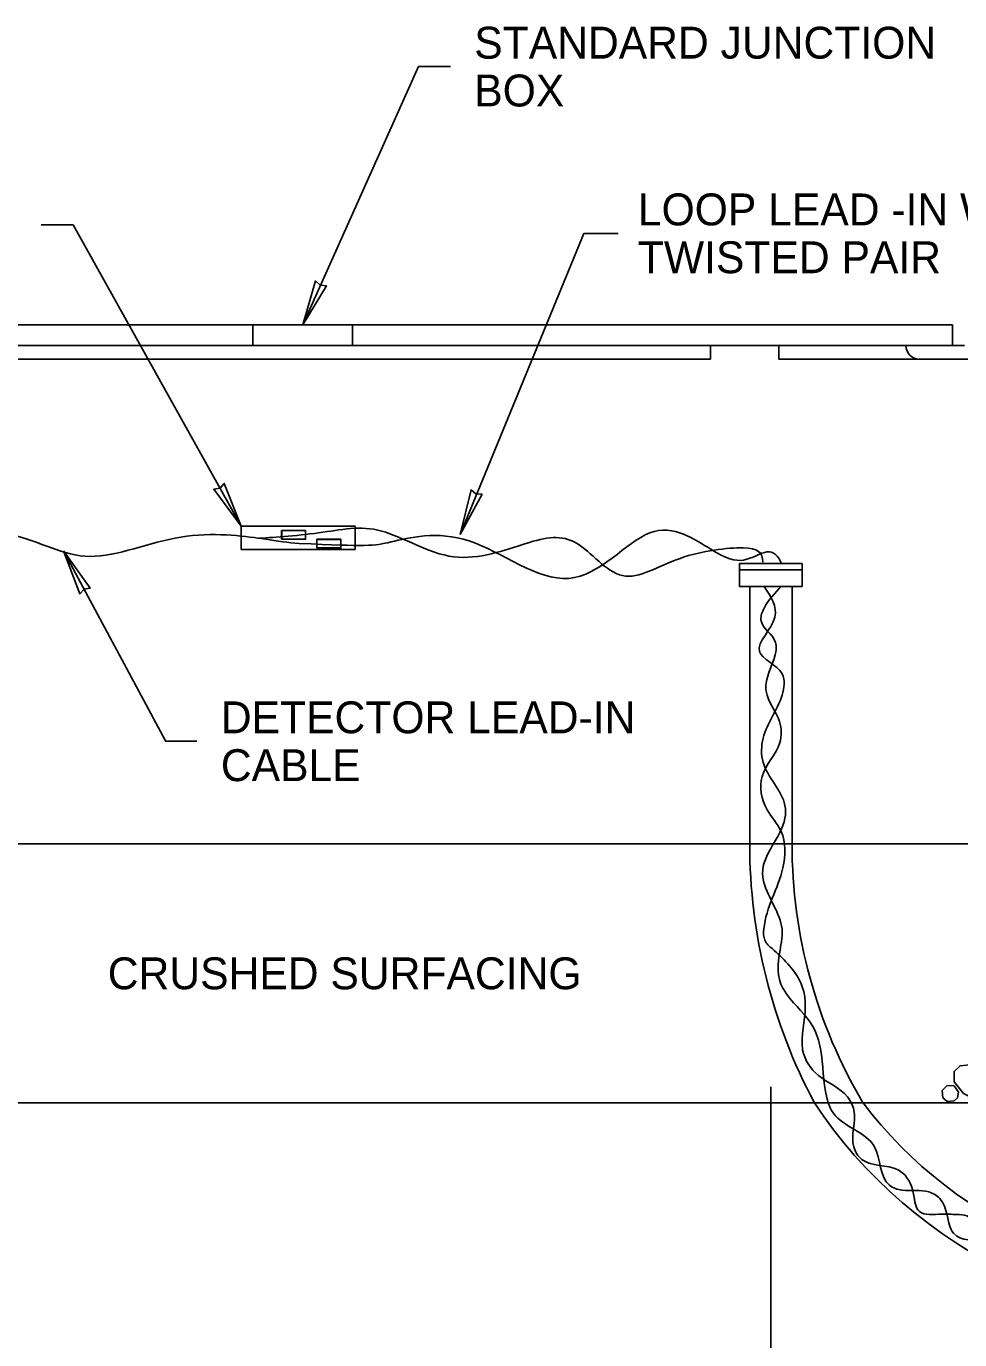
# Model space of a CAD drawing. Extents: x 99862 to 103151, y 100000 to 108153.
# Drawn here: x 101003 to 101472, y 100351 to 101010 of the extents above; entities that cross this region are included whole.
import ezdxf

# ---------------------------------------------------------------- set-up
doc = ezdxf.new("R2010")
doc.units = 0
for name, color, linetype in [('Level 10', 7, 'Continuous'), ('Level 11', 7, 'Continuous'), ('Level 12', 7, 'Continuous'), ('Level 13', 7, 'Continuous'), ('Level 15', 7, 'Continuous'), ('Level 2', 7, 'Continuous'), ('Level 20', 7, 'Continuous'), ('Level 22', 7, 'Continuous'), ('Level 3', 7, 'Continuous'), ('Level 5', 7, 'Continuous')]:
    doc.layers.add(name, color=color, linetype=linetype)

msp = doc.modelspace()

# ---------------------------------------------------------------- linework, layer by layer
at = {"layer": 'Level 10'}
for p, q in [((101366.46, 100599.88), (101366.46, 100729.02)), ((101387.71, 100599.88), (101387.71, 100729.02))]:
    msp.add_line(p, q, dxfattribs=at)
for radius, end in [(276.25, 208.06023), (255, 210.63538)]:
    msp.add_arc((101642.71, 100599.88), radius, 180, end, dxfattribs=at)
for centre, major_axis, ratio, start_param in [((101642.71, 100576.59), (276.25, 0), 0.820889, 3.63155), ((101642.71, 100572.63), (255, 0), 0.79044, 3.67655)]:
    msp.add_ellipse(centre, major_axis=major_axis, ratio=ratio, start_param=start_param, end_param=4.712389, dxfattribs=at)
at = {"layer": 'Level 11'}
for points in [[(100765.96, 100599.88), (101570.21, 100599.88), (101570.21, 100469.88), (100765.96, 100469.88)], [(101485.29, 100486.31), (101478.37, 100489.06), (101472.02, 100488.51), (101469, 100485.64), (101469.09, 100480.48), (101473.68, 100474.62), (101480.76, 100471.08), (101487.44, 100470.96), (101491.19, 100473.63), (101491.55, 100478.95), (101488.5, 100483.71), (101485.01, 100486.49)], [(101471.25, 100475.22), (101469.03, 100478.37), (101465.49, 100478.57), (101463.02, 100476.02), (101463.38, 100472.44), (101465.57, 100470.62), (101469.06, 100470.88), (101470.71, 100472.47), (101471.25, 100475.21)]]:
    msp.add_lwpolyline(points, dxfattribs=at)
at = {"layer": 'Level 12'}
for points in [[(101131.61, 100756.99), (101131.61, 100752.69), (101143.58, 100752.69), (101143.58, 100756.99)], [(101149.25, 100752.62), (101149.25, 100748.32), (101161.21, 100748.32), (101161.21, 100752.62)]]:
    msp.add_lwpolyline(points, close=True, dxfattribs=at)
for points in [[(100952.08, 100740.57), (100962.16, 100757.68), (100999.6, 100759.06), (101032.8, 100736.71), (101081.48, 100758.42), (101127.45, 100752.25), (101134.35, 100751.01), (101140.37, 100750.57)], [(101372.99, 100741.12), (101372.99, 100746.31), (101368.37, 100749.92), (101329.85, 100745.59), (101301.51, 100726.14), (101279.67, 100756.49), (101256.78, 100752.36), (101217.46, 100737.22), (101180.28, 100762.05), (101152.19, 100755.14), (101125.28, 100753.42), (101120.16, 100753.17)], [(101140.37, 100750.57), (101174.61, 100749.05), (101180.88, 100749.48), (101223.84, 100761.03), (101278.23, 100717.14), (101317.44, 100768.39), (101350.05, 100744.44), (101363.63, 100740), (101375.91, 100748.89), (101380.85, 100744.59), (101382.47, 100740.46)]]:
    msp.add_open_spline(points, degree=3, dxfattribs=at)
for points in [[(101373.71, 100728.96), (101379.12, 100713.53), (101371.32, 100696.39), (101382.72, 100685.15), (101382.72, 100674.48), (101373.2, 100652.84), (101373.2, 100640.72), (101384.16, 100619.07), (101384.16, 100612.72), (101372.9, 100585.02), (101374.06, 100578.96), (101382.78, 100555.64), (101382.15, 100549.11)], [(101382.39, 100729.13), (101373.7, 100718.1), (101372.11, 100712.25), (101379.47, 100700.85), (101379.25, 100694.64), (101374.71, 100680.45), (101374.71, 100676.41), (101381.41, 100661.17), (101381.56, 100650.64), (101372.69, 100633.7), (101375.15, 100616.97), (101382.21, 100606.07), (101383.07, 100587.82), (101373.55, 100557.23), (101374.09, 100551.45), (101375.57, 100549.1)], [(101375.57, 100549.1), (101390.43, 100533.21), (101393.61, 100525.71), (101393.03, 100504.66), (101393.03, 100496.56), (101400.96, 100483.6), (101415.54, 100472.9), (101418.71, 100466.26), (101418.71, 100447.79), (101422.75, 100441.45), (101440.89, 100436.29), (101448.14, 100426.44), (101451.69, 100415.3), (101462.79, 100414.08), (101470.32, 100413.86), (101475.42, 100413.17), (101484.69, 100395.83), (101495.49, 100388.53), (101513.75, 100389.29), (101525.46, 100387.77), (101542.5, 100369.67), (101551.77, 100371.19), (101566.71, 100375.02), (101575.8, 100371.55), (101590.69, 100360.3), (101595.6, 100360.3), (101622.33, 100365.21), (101628.49, 100364.99), (101645.23, 100353.37), (101652.45, 100353.37), (101681.59, 100367.8)], [(101382.15, 100549.11), (101382.15, 100529.46), (101385.24, 100524.12), (101398.08, 100508.25), (101401.97, 100496.99), (101405.15, 100472.47), (101408.47, 100464.68), (101429.1, 100447.79), (101436.63, 100428.53), (101442.95, 100426.1), (101456.4, 100425.19), (101461.88, 100421.84), (101465.53, 100413.48), (101468.72, 100404.5), (101486.21, 100400.7), (101499.22, 100398.27), (101510.7, 100386.65), (101518.77, 100377.73), (101547.99, 100380.21), (101551.59, 100377.75), (101562.7, 100364.04), (101571.9, 100363.43), (101592.97, 100369.1), (101605.52, 100365.85), (101624.89, 100355.61), (101629, 100355.61), (101653.89, 100363.76), (101657.93, 100363.76), (101693.57, 100351.06)]]:
    msp.add_spline(points, degree=3, dxfattribs=at)
at = {"layer": 'Level 13'}
for p, q in [((101361.4, 100740.57), (101392.76, 100740.57)), ((101361.4, 100740.57), (101361.4, 100737.27)), ((101392.76, 100737.27), (101361.4, 100737.27)), ((101361.4, 100737.27), (101392.76, 100737.27)), ((101361.4, 100729.02), (101361.4, 100737.27)), ((101361.4, 100737.27), (101392.76, 100737.27)), ((101388.08, 100737.27), (101366.08, 100737.27)), ((101366.08, 100737.27), (101388.08, 100737.27)), ((101392.76, 100740.57), (101392.76, 100737.27)), ((101392.76, 100729.02), (101392.76, 100737.27)), ((101392.76, 100729.02), (101361.4, 100729.02)), ((101361.4, 100729.02), (101392.76, 100729.02)), ((101388.08, 100729.02), (101366.08, 100729.02))]:
    msp.add_line(p, q, dxfattribs=at)
at = {"layer": 'Level 15'}
for p, q in [((101142.12, 100860.19), (101200.24, 100989.81)), ((101216.24, 100989.81), (101200.24, 100989.81)), ((101010.96, 100910.38), (101026.96, 100910.38)), ((101111.26, 100759.28), (101026.96, 100910.38)), ((101283.16, 100906.15), (101300.39, 100906.15)), ((101073.26, 100651.47), (101022.1, 100746.87)), ((101073.06, 100651.31), (101089.06, 100651.31))]:
    msp.add_line(p, q, dxfattribs=at)
for points in [[(101283.16, 100906.15), (101221.1, 100755.1)], [(101377.08, 100215.73), (101377.08, 100478)]]:
    msp.add_lwpolyline(points, dxfattribs=at)
for points in [[(101142.12, 100860.19), (101148.57, 100882.29), (101150.88, 100880.12), (101154.04, 100879.89)], [(101111.26, 100759.28), (101097.53, 100777.76), (101100.65, 100778.29), (101102.74, 100780.67)], [(101221.1, 100755.1), (101226.62, 100777.45), (101229.01, 100775.38), (101232.18, 100775.28)], [(101022.1, 100746.87), (101030.26, 100725.34), (101032.39, 100727.68), (101035.52, 100728.16)]]:
    msp.add_lwpolyline(points, close=True, dxfattribs=at)
at = {"layer": 'Level 2'}
for p, q in [((100922.62, 100849.85), (101474.21, 100849.85)), ((101346.77, 100849.81), (101346.77, 100849.85)), ((101346.77, 100843.07), (101346.77, 100849.81)), ((101381.14, 100849.85), (101381.14, 100849.81)), ((101381.14, 100849.81), (101381.14, 100843.07)), ((101178.22, 100843.07), (100902.18, 100843.07)), ((101346.77, 100843.07), (101178.22, 100843.07)), ((101451.62, 100843.07), (101381.14, 100843.07)), ((101479.26, 100843.07), (101451.62, 100843.07))]:
    msp.add_line(p, q, dxfattribs=at)
msp.add_arc((101451.62, 100849.81), 6.74, 180, 270, dxfattribs=at)
at = {"layer": 'Level 22'}
msp.add_line((101387.71, 100729.02), (101366.46, 100729.02), dxfattribs=at)
at = {"layer": 'Level 3'}
for p, q in [((100927.18, 100860.19), (101468.22, 100860.19)), ((101117.18, 100849.86), (101117.18, 100860.19)), ((101117.18, 100860.19), (101167.06, 100860.19)), ((101167.06, 100860.19), (101167.06, 100849.86)), ((101468.22, 100860.19), (101468.22, 100849.85))]:
    msp.add_line(p, q, dxfattribs=at)
at = {"layer": 'Level 5'}
for points in [[(101111.26, 100759.28), (101168.39, 100759.28), (101168.39, 100747.58), (101111.26, 100747.58)], [(101131.57, 100757), (101143.61, 100757), (101143.61, 100752.65), (101131.57, 100752.65)], [(101149.24, 100752.65), (101161.28, 100752.65), (101161.28, 100748.3), (101149.24, 100748.3)]]:
    msp.add_lwpolyline(points, close=True, dxfattribs=at)

# ---------------------------------------------------------------- texts
at = {"layer": 'Level 20'}
for s, rotation, p in [('STANDARD JUNCTION', 360, (101228.24, 100993.81)), ('BOX', 360, (101228.24, 100969.81)), ('LOOP LEAD -IN WIRES ', 359.99999, (101310.33, 100910.15)), ('TWISTED PAIR', 359.99999, (101310.33, 100886.15))]:
    msp.add_text(s, height=16, rotation=rotation, dxfattribs=at).set_placement(p)
for s, p in [('DETECTOR LEAD-IN', (101101.06, 100655.31)), ('CABLE', (101101.06, 100631.31)), ('CRUSHED SURFACING', (101044.3, 100526.88))]:
    msp.add_text(s, height=16, dxfattribs=at).set_placement(p)

doc.saveas('drawing.dxf')
